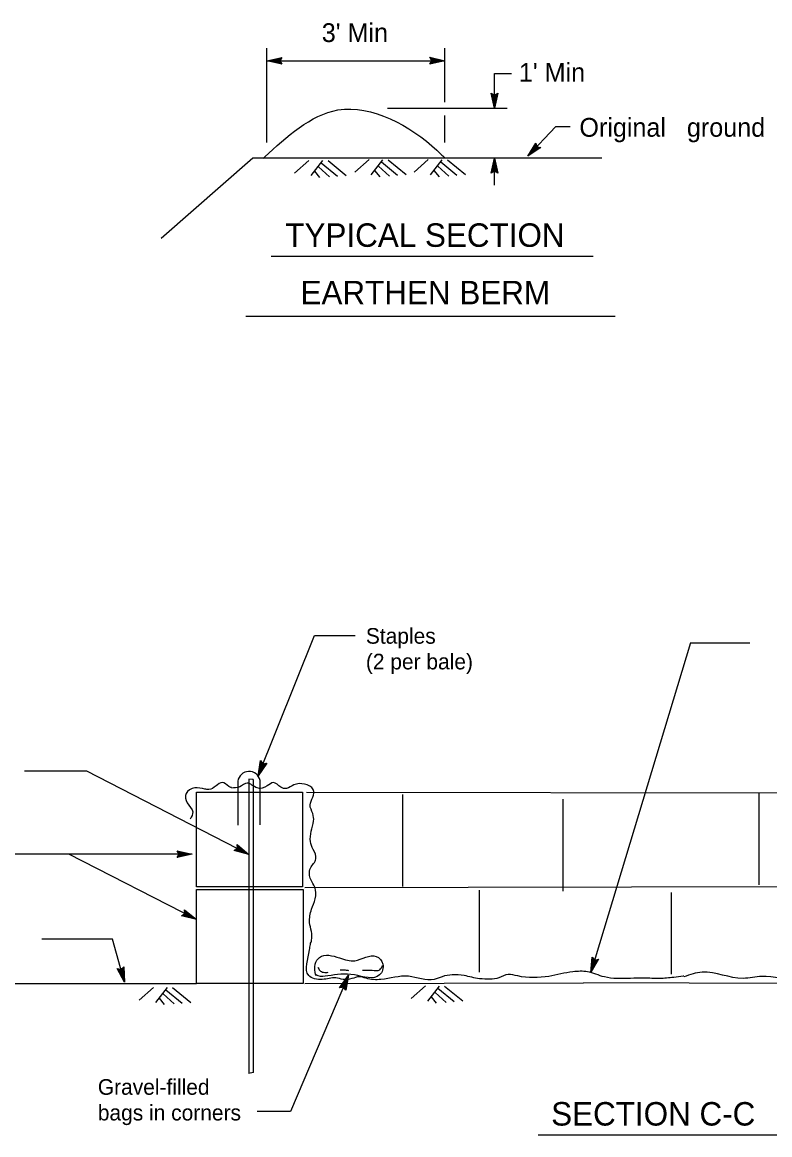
# Model space of a CAD drawing. Extents: x 6708826 to 6711089, y 1868571 to 1869537.
# Drawn here: x 6709428.3 to 6709714.7, y 1869091.6 to 1869517.9 of the extents above; entities that cross this region are included whole.
import ezdxf

# ---------------------------------------------------------------- set-up
doc = ezdxf.new("R2010")
doc.units = 0
for name, color, linetype in [('1 Control', 7, 'Continuous'), ('56 Stg 3 Anno', 7, 'Continuous'), ('57 Undefined', 7, 'Continuous'), ('59 Soundwall Ann', 7, 'Continuous'), ('60 Nongeo Data', 7, 'Continuous')]:
    doc.layers.add(name, color=color, linetype=linetype)

msp = doc.modelspace()

# ---------------------------------------------------------------- linework, layer by layer
at = {"layer": '1 Control'}
for p, q in [((6709487.66, 1869200.39), (6709487.66, 1869200.39)), ((6709487.66, 1869197.83), (6709487.66, 1869197.83)), ((6709493.42, 1869199.11), (6709493.42, 1869199.11))]:
    msp.add_line(p, q, dxfattribs=at)
msp.add_lwpolyline([(6709487.66, 1869200.39), (6709493.42, 1869199.11), (6709487.66, 1869197.83), (6709487.86, 1869198.17), (6709492.08, 1869199.1), (6709487.86, 1869200.05), (6709488.07, 1869199.71), (6709490.77, 1869199.11), (6709488.07, 1869198.51), (6709488.27, 1869198.85), (6709489.44, 1869199.11), (6709488.27, 1869199.37), (6709488.43, 1869199.11), (6709487.66, 1869197.83), (6709488.43, 1869199.11)], close=True, dxfattribs=at)
at = {"layer": '56 Stg 3 Anno'}
for p, q in [((6709521.95, 1869471.87), (6709521.95, 1869508.01)), ((6709590.2, 1869487.34), (6709590.2, 1869508.01)), ((6709521.95, 1869503.21), (6709527.71, 1869504.49)), ((6709521.95, 1869503.21), (6709590.2, 1869503.21)), ((6709527.71, 1869501.92), (6709521.95, 1869503.21)), ((6709521.95, 1869503.21), (6709521.95, 1869503.21)), ((6709527.51, 1869502.26), (6709523.28, 1869503.21)), ((6709523.29, 1869503.21), (6709527.49, 1869504.14)), ((6709524.61, 1869503.21), (6709527.32, 1869503.81)), ((6709527.28, 1869502.61), (6709524.61, 1869503.21)), ((6709525.93, 1869503.21), (6709527.09, 1869503.46)), ((6709527.11, 1869502.94), (6709525.93, 1869503.21)), ((6709527.71, 1869504.49), (6709526.95, 1869503.21)), ((6709526.95, 1869503.21), (6709527.71, 1869501.92)), ((6709527.71, 1869504.49), (6709527.71, 1869504.49)), ((6709585.21, 1869503.21), (6709584.44, 1869504.5)), ((6709584.44, 1869504.5), (6709584.44, 1869504.5)), ((6709584.44, 1869504.5), (6709590.2, 1869503.21)), ((6709590.2, 1869503.21), (6709584.44, 1869501.93)), ((6709584.44, 1869501.93), (6709585.21, 1869503.21)), ((6709584.65, 1869504.15), (6709588.87, 1869503.21)), ((6709588.86, 1869503.21), (6709584.66, 1869502.28)), ((6709587.55, 1869503.21), (6709584.83, 1869502.61)), ((6709584.87, 1869503.81), (6709587.55, 1869503.21)), ((6709585.04, 1869503.48), (6709586.22, 1869503.21)), ((6709586.22, 1869503.21), (6709585.06, 1869502.96)), ((6709590.2, 1869503.21), (6709590.2, 1869503.21)), ((6709527.71, 1869501.92), (6709527.71, 1869501.92)), ((6709584.44, 1869501.93), (6709584.44, 1869501.93)), ((6709609.25, 1869485.06), (6709609.25, 1869498.24)), ((6709609.25, 1869498.24), (6709615.67, 1869498.24)), ((6709609.25, 1869485.06), (6709607.98, 1869490.82)), ((6709607.98, 1869490.82), (6709607.98, 1869490.82)), ((6709607.98, 1869490.82), (6709609.25, 1869490.05)), ((6709609.25, 1869486.4), (6709608.32, 1869490.6)), ((6709609.26, 1869487.71), (6709608.65, 1869490.43)), ((6709609.26, 1869489.04), (6709609, 1869490.2)), ((6709609.25, 1869490.05), (6709610.54, 1869490.82)), ((6709610.54, 1869490.82), (6709609.25, 1869485.06)), ((6709610.2, 1869490.61), (6709609.25, 1869486.39)), ((6709609.85, 1869490.39), (6709609.26, 1869487.71)), ((6709609.52, 1869490.22), (6709609.26, 1869489.04)), ((6709610.54, 1869490.82), (6709610.54, 1869490.82)), ((6709568.17, 1869485.06), (6709614.05, 1869485.06)), ((6709590.2, 1869471.87), (6709590.2, 1869482.26)), ((6709609.25, 1869485.06), (6709609.25, 1869485.06)), ((6709622.02, 1869466.58), (6709632.64, 1869477.8)), ((6709638.16, 1869477.8), (6709632.64, 1869477.8)), ((6709622.02, 1869466.58), (6709625.05, 1869471.64)), ((6709626.92, 1869469.88), (6709622.02, 1869466.58)), ((6709626.52, 1869469.96), (6709622.93, 1869467.54)), ((6709622.94, 1869467.55), (6709625.15, 1869471.24)), ((6709623.85, 1869468.5), (6709625.27, 1869470.89)), ((6709626.12, 1869470.04), (6709623.85, 1869468.5)), ((6709624.76, 1869469.47), (6709625.37, 1869470.48)), ((6709625.76, 1869470.14), (6709624.76, 1869469.47)), ((6709625.05, 1869471.64), (6709625.05, 1869471.64)), ((6709625.05, 1869471.64), (6709625.45, 1869470.2)), ((6709625.45, 1869470.2), (6709626.92, 1869469.88)), ((6709626.92, 1869469.88), (6709626.92, 1869469.88)), ((6709607.97, 1869460.1), (6709609.25, 1869465.86)), ((6709608.31, 1869460.3), (6709609.25, 1869464.53)), ((6709609.25, 1869465.86), (6709609.25, 1869465.86)), ((6709609.25, 1869465.86), (6709610.53, 1869460.1)), ((6709609.25, 1869455.51), (6709609.25, 1869465.86)), ((6709609.26, 1869464.52), (6709610.19, 1869460.32)), ((6709622.02, 1869466.58), (6709622.02, 1869466.58)), ((6709609.25, 1869460.86), (6709607.97, 1869460.1)), ((6709607.97, 1869460.1), (6709607.97, 1869460.1)), ((6709608.65, 1869460.53), (6709609.25, 1869463.2)), ((6709608.99, 1869460.7), (6709609.25, 1869461.88)), ((6709609.25, 1869463.2), (6709609.85, 1869460.49)), ((6709609.25, 1869461.88), (6709609.51, 1869460.72)), ((6709610.53, 1869460.1), (6709609.25, 1869460.86)), ((6709610.53, 1869460.1), (6709610.53, 1869460.1)), ((6709518.59, 1869229.13), (6709540.27, 1869282.85)), ((6709540.27, 1869282.85), (6709555.82, 1869282.85)), ((6709684.34, 1869280.08), (6709646.13, 1869153.7)), ((6709684.34, 1869280.08), (6709707, 1869280.08)), ((6709518.59, 1869229.13), (6709519.56, 1869234.95)), ((6709521.94, 1869233.99), (6709518.59, 1869229.13)), ((6709519.08, 1869230.37), (6709519.79, 1869234.61)), ((6709521.54, 1869233.92), (6709519.08, 1869230.36)), ((6709519.56, 1869234.95), (6709519.56, 1869234.95)), ((6709519.56, 1869234.95), (6709520.46, 1869233.76)), ((6709519.58, 1869231.59), (6709520.04, 1869234.33)), ((6709520.08, 1869232.82), (6709520.27, 1869233.99)), ((6709520.46, 1869233.76), (6709521.94, 1869233.99)), ((6709521.94, 1869233.99), (6709521.94, 1869233.99)), ((6709453.01, 1869230.92), (6709429.07, 1869230.92)), ((6709515.11, 1869199.03), (6709453.01, 1869230.92)), ((6709521.14, 1869233.85), (6709519.58, 1869231.59)), ((6709520.77, 1869233.81), (6709520.08, 1869232.82)), ((6709518.59, 1869229.13), (6709518.59, 1869229.13)), ((6709509.4, 1869200.52), (6709510.67, 1869201.31)), ((6709515.11, 1869199.03), (6709509.4, 1869200.52)), ((6709509.4, 1869200.52), (6709509.4, 1869200.52)), ((6709513.92, 1869199.64), (6709509.76, 1869200.73)), ((6709512.75, 1869200.24), (6709510.07, 1869200.95)), ((6709511.57, 1869200.85), (6709510.42, 1869201.15)), ((6709510.67, 1869201.31), (6709510.58, 1869202.8)), ((6709510.58, 1869202.8), (6709510.58, 1869202.8)), ((6709510.58, 1869202.8), (6709515.11, 1869199.03)), ((6709510.6, 1869202.41), (6709513.93, 1869199.63)), ((6709510.65, 1869202), (6709512.75, 1869200.24)), ((6709510.65, 1869201.62), (6709511.57, 1869200.85)), ((6709493.42, 1869199.11), (6709417.73, 1869199.11)), ((6709494.96, 1869174), (6709446.06, 1869199.11)), ((6709515.11, 1869199.03), (6709515.11, 1869199.03)), ((6709489.25, 1869175.49), (6709490.52, 1869176.28)), ((6709494.96, 1869174), (6709489.25, 1869175.49)), ((6709489.25, 1869175.49), (6709489.25, 1869175.49)), ((6709493.77, 1869174.6), (6709489.61, 1869175.7)), ((6709492.6, 1869175.21), (6709489.91, 1869175.91)), ((6709491.42, 1869175.82), (6709490.27, 1869176.12)), ((6709490.52, 1869176.28), (6709490.42, 1869177.77)), ((6709490.42, 1869177.77), (6709490.42, 1869177.77)), ((6709490.42, 1869177.77), (6709494.96, 1869174)), ((6709490.45, 1869177.37), (6709493.78, 1869174.6)), ((6709490.49, 1869176.96), (6709492.6, 1869175.21)), ((6709490.49, 1869176.59), (6709491.42, 1869175.82)), ((6709494.96, 1869174), (6709494.96, 1869174)), ((6709462.84, 1869166.47), (6709435.69, 1869166.47)), ((6709467.42, 1869150.02), (6709462.84, 1869166.47)), ((6709646.13, 1869153.7), (6709646.57, 1869159.58)), ((6709649.03, 1869158.84), (6709646.13, 1869153.7)), ((6709646.51, 1869154.98), (6709646.84, 1869159.27)), ((6709648.64, 1869158.74), (6709646.51, 1869154.97)), ((6709646.57, 1869159.58), (6709646.57, 1869159.58)), ((6709646.57, 1869159.58), (6709647.57, 1869158.48)), ((6709646.9, 1869156.24), (6709647.11, 1869159.01)), ((6709648.24, 1869158.63), (6709646.9, 1869156.24)), ((6709647.28, 1869157.51), (6709647.37, 1869158.69)), ((6709647.88, 1869158.56), (6709647.28, 1869157.51)), ((6709647.57, 1869158.48), (6709649.03, 1869158.84)), ((6709649.03, 1869158.84), (6709649.03, 1869158.84)), ((6709467.42, 1869150.02), (6709464.64, 1869155.23)), ((6709464.64, 1869155.23), (6709464.64, 1869155.23)), ((6709464.64, 1869155.23), (6709466.08, 1869154.83)), ((6709467.06, 1869151.31), (6709465.04, 1869155.11)), ((6709466.71, 1869152.58), (6709465.4, 1869155.03)), ((6709466.35, 1869153.86), (6709465.8, 1869154.91)), ((6709466.08, 1869154.83), (6709467.11, 1869155.92)), ((6709466.29, 1869155.07), (6709466.35, 1869153.86)), ((6709466.57, 1869155.32), (6709466.71, 1869152.58)), ((6709466.84, 1869155.63), (6709467.06, 1869151.3)), ((6709467.11, 1869155.92), (6709467.11, 1869155.92)), ((6709467.11, 1869155.92), (6709467.42, 1869150.02)), ((6709646.13, 1869153.7), (6709646.13, 1869153.7)), ((6709467.42, 1869150.02), (6709467.42, 1869150.02)), ((6709553.27, 1869152.72), (6709531.07, 1869100.43)), ((6709549.84, 1869147.92), (6709553.27, 1869152.72)), ((6709550.23, 1869147.98), (6709552.75, 1869151.5)), ((6709550.64, 1869148.05), (6709552.23, 1869150.28)), ((6709551.01, 1869148.08), (6709551.71, 1869149.06)), ((6709551.71, 1869149.06), (6709551.5, 1869147.89)), ((6709552.23, 1869150.28), (6709551.73, 1869147.55)), ((6709552.75, 1869151.49), (6709551.97, 1869147.26)), ((6709553.27, 1869152.72), (6709552.2, 1869146.92)), ((6709553.27, 1869152.72), (6709553.27, 1869152.72)), ((6709551.32, 1869148.12), (6709549.84, 1869147.92)), ((6709549.84, 1869147.92), (6709549.84, 1869147.92)), ((6709552.2, 1869146.92), (6709551.32, 1869148.12)), ((6709552.2, 1869146.92), (6709552.2, 1869146.92)), ((6709531.07, 1869100.43), (6709518.32, 1869100.43))]:
    msp.add_line(p, q, dxfattribs=at)
at = {"layer": '57 Undefined'}
for p, q in [((6709523.66, 1869428.34), (6709646.96, 1869428.34)), ((6709513.9, 1869405.34), (6709655.5, 1869405.34)), ((6709625.91, 1869091.56), (6709719.89, 1869091.56))]:
    msp.add_line(p, q, dxfattribs=at)
at = {"layer": '59 Soundwall Ann'}
for p, q in [((6709538.1, 1869464.97), (6709532.62, 1869460.09)), ((6709543.3, 1869464.93), (6709538.78, 1869459.18)), ((6709545.41, 1869464.91), (6709552.33, 1869459.21)), ((6709561.14, 1869465.31), (6709555.66, 1869460.43)), ((6709566.33, 1869465.27), (6709561.82, 1869459.52)), ((6709565.89, 1869464.41), (6709572.08, 1869459.31)), ((6709568.44, 1869465.25), (6709575.37, 1869459.55)), ((6709583.84, 1869465.31), (6709578.36, 1869460.43)), ((6709589.03, 1869465.27), (6709584.52, 1869459.52)), ((6709588.59, 1869464.41), (6709594.78, 1869459.31)), ((6709591.14, 1869465.25), (6709598.06, 1869459.55)), ((6709540.22, 1869460.83), (6709542.2, 1869458.4)), ((6709541.72, 1869462.48), (6709545.95, 1869458.63)), ((6709542.85, 1869464.07), (6709549.04, 1869458.97)), ((6709563.26, 1869461.17), (6709565.24, 1869458.74)), ((6709564.76, 1869462.82), (6709568.98, 1869458.97)), ((6709585.96, 1869461.17), (6709587.94, 1869458.74)), ((6709587.46, 1869462.82), (6709591.68, 1869458.97)), ((6709478.57, 1869148.02), (6709473.1, 1869143.15)), ((6709483.77, 1869147.99), (6709479.25, 1869142.24)), ((6709482.19, 1869145.54), (6709486.42, 1869141.69)), ((6709483.32, 1869147.13), (6709489.51, 1869142.03)), ((6709485.88, 1869147.96), (6709492.8, 1869142.26)), ((6709582.79, 1869148.59), (6709577.31, 1869143.72)), ((6709587.99, 1869148.55), (6709583.47, 1869142.81)), ((6709584.91, 1869144.46), (6709586.89, 1869142.03)), ((6709586.41, 1869146.11), (6709590.64, 1869142.26)), ((6709587.54, 1869147.69), (6709593.73, 1869142.6)), ((6709590.09, 1869148.53), (6709597.02, 1869142.83)), ((6709480.69, 1869143.89), (6709482.67, 1869141.46))]:
    msp.add_line(p, q, dxfattribs=at)
at = {"layer": '60 Nongeo Data'}
for p, q in [((6709516.63, 1869465.86), (6709481.54, 1869435.01)), ((6709650.32, 1869465.86), (6709516.63, 1869465.86)), ((6709510.85, 1869227.15), (6709510.85, 1869210.15)), ((6709515.11, 1869227.84), (6709515.11, 1869115.08)), ((6709516.73, 1869227.73), (6709515.11, 1869227.84)), ((6709516.73, 1869227.61), (6709516.73, 1869227.84)), ((6709516.73, 1869227.61), (6709516.73, 1869115.4)), ((6709519.43, 1869210.39), (6709519.43, 1869227.39)), ((6709537.12, 1869222.92), (6709807.06, 1869222.39)), ((6709573.96, 1869221.95), (6709573.96, 1869186.7)), ((6709710.44, 1869222.62), (6709710.44, 1869187.36)), ((6709635.34, 1869220.22), (6709635.34, 1869184.96)), ((6709536.5, 1869186.34), (6709806.17, 1869186.87)), ((6709603.37, 1869185.26), (6709603.37, 1869153.89)), ((6709676.87, 1869184.46), (6709676.87, 1869153.09)), ((6709365.05, 1869149.57), (6709494.96, 1869149.57)), ((6709536.5, 1869149.54), (6709643.26, 1869149.81)), ((6709806.03, 1869149.33), (6709643.26, 1869149.74)), ((6709516.82, 1869115.44), (6709514.99, 1869115.08))]:
    msp.add_line(p, q, dxfattribs=at)
for points in [[(6709494.96, 1869222.81), (6709535.59, 1869222.81), (6709535.59, 1869186.56), (6709494.96, 1869186.56)], [(6709494.96, 1869185.61), (6709535.89, 1869185.61), (6709535.89, 1869149.57), (6709494.96, 1869149.57)]]:
    msp.add_lwpolyline(points, close=True, dxfattribs=at)
msp.add_arc((6709515.15, 1869226.45), 4.36, 12.0716, 172.0722, dxfattribs=at)
for points in [[(6709520.62, 1869465.86), (6709521.18, 1869466.37), (6709549.23, 1869484.31), (6709587.12, 1869468.88), (6709590.2, 1869465.94)], [(6709508.47, 1869224.6), (6709507.47, 1869225.08), (6709504.91, 1869226.59), (6709502.49, 1869225.23), (6709499.77, 1869223.88), (6709498.26, 1869224.03), (6709494.34, 1869224.48), (6709491.02, 1869222.37), (6709491.47, 1869218.75), (6709493.58, 1869215.28), (6709492.65, 1869212.52)], [(6709630.08, 1869152.2), (6709618.1, 1869152.41), (6709614.47, 1869153.02), (6709610.85, 1869151.66), (6709607.53, 1869151.21), (6709603.45, 1869151.36), (6709597.56, 1869152.57), (6709593.04, 1869152.87), (6709589.11, 1869152.11), (6709586.09, 1869151.06), (6709576.22, 1869152.3), (6709565.71, 1869151.06), (6709559.97, 1869151.51), (6709557.41, 1869152.11), (6709554.53, 1869151.38), (6709551.17, 1869151.07), (6709548.42, 1869151.68), (6709543.22, 1869151.07), (6709538.03, 1869152.6), (6709538.34, 1869162.38), (6709538.64, 1869164.52), (6709539.14, 1869166.13), (6709538.38, 1869172.91), (6709539.14, 1869178.03), (6709540.5, 1869181.95), (6709540.35, 1869186.47), (6709538.84, 1869189.33), (6709538.68, 1869193.7), (6709540.8, 1869197.31), (6709539.74, 1869200.93), (6709538.68, 1869203.94), (6709538.99, 1869207.86), (6709539.89, 1869211.78), (6709539.59, 1869214.64), (6709538.53, 1869217.96), (6709539.59, 1869220.97), (6709539.74, 1869223.83), (6709536.42, 1869225.94), (6709532.34, 1869225.64), (6709529.48, 1869224.29), (6709527.36, 1869224.74), (6709524.49, 1869226.55), (6709522.14, 1869225.24), (6709518.21, 1869224.49), (6709514.44, 1869226.3), (6709511.57, 1869224.94), (6709508.4, 1869224.43)], [(6709540.73, 1869152.62), (6709540.54, 1869156.99), (6709542.19, 1869159.54), (6709549.85, 1869159.36), (6709555.69, 1869158.26), (6709563.9, 1869159.9), (6709566.46, 1869156.99), (6709565.18, 1869152.8), (6709555.51, 1869152.8), (6709545.29, 1869152.43), (6709541.64, 1869152.43), (6709540.91, 1869152.8)], [(6709541.52, 1869155.82), (6709542.25, 1869154.54), (6709543.71, 1869153.82), (6709545.53, 1869153.82)], [(6709550.03, 1869154.73), (6709552.04, 1869154.73), (6709553.32, 1869154.55)], [(6709558.67, 1869154.61), (6709562.32, 1869154.61), (6709565.24, 1869154.79), (6709566.34, 1869156.43)], [(6709681.79, 1869152.4), (6709681.51, 1869152.34), (6709677.88, 1869151.89), (6709672.45, 1869151.44), (6709666.41, 1869151.59), (6709656.15, 1869151.44), (6709651.32, 1869152.04), (6709644.83, 1869154), (6709639.24, 1869154), (6709630.03, 1869152.19)], [(6709730.16, 1869152.32), (6709725.65, 1869151.13), (6709711.6, 1869152.22), (6709704.48, 1869151.49), (6709688.79, 1869153.86), (6709681.77, 1869152.08)]]:
    msp.add_spline(points, degree=3, dxfattribs=at)

# ---------------------------------------------------------------- texts
at = {"layer": '57 Undefined'}
for s, height, p in [("3' Min", 7.2, (6709543.03, 1869510.35)), ("1' Min", 7.2, (6709618.55, 1869495.11)), ('Original   ground', 7.2002, (6709641.73, 1869474.06)), ('TYPICAL SECTION', 9, (6709529.06, 1869431.86)), ('EARTHEN BERM', 9, (6709534.88, 1869409.82)), ('Staples', 6, (6709559.92, 1869279.75)), ('(2 per bale)', 6, (6709559.92, 1869269.91)), ('Gravel-filled', 6, (6709457.21, 1869106.87)), ('bags in corners', 6, (6709457.21, 1869097.03)), ('SECTION C-C', 9, (6709630.92, 1869095.08))]:
    msp.add_text(s, height=height, dxfattribs=at).set_placement(p)

doc.saveas('drawing.dxf')
